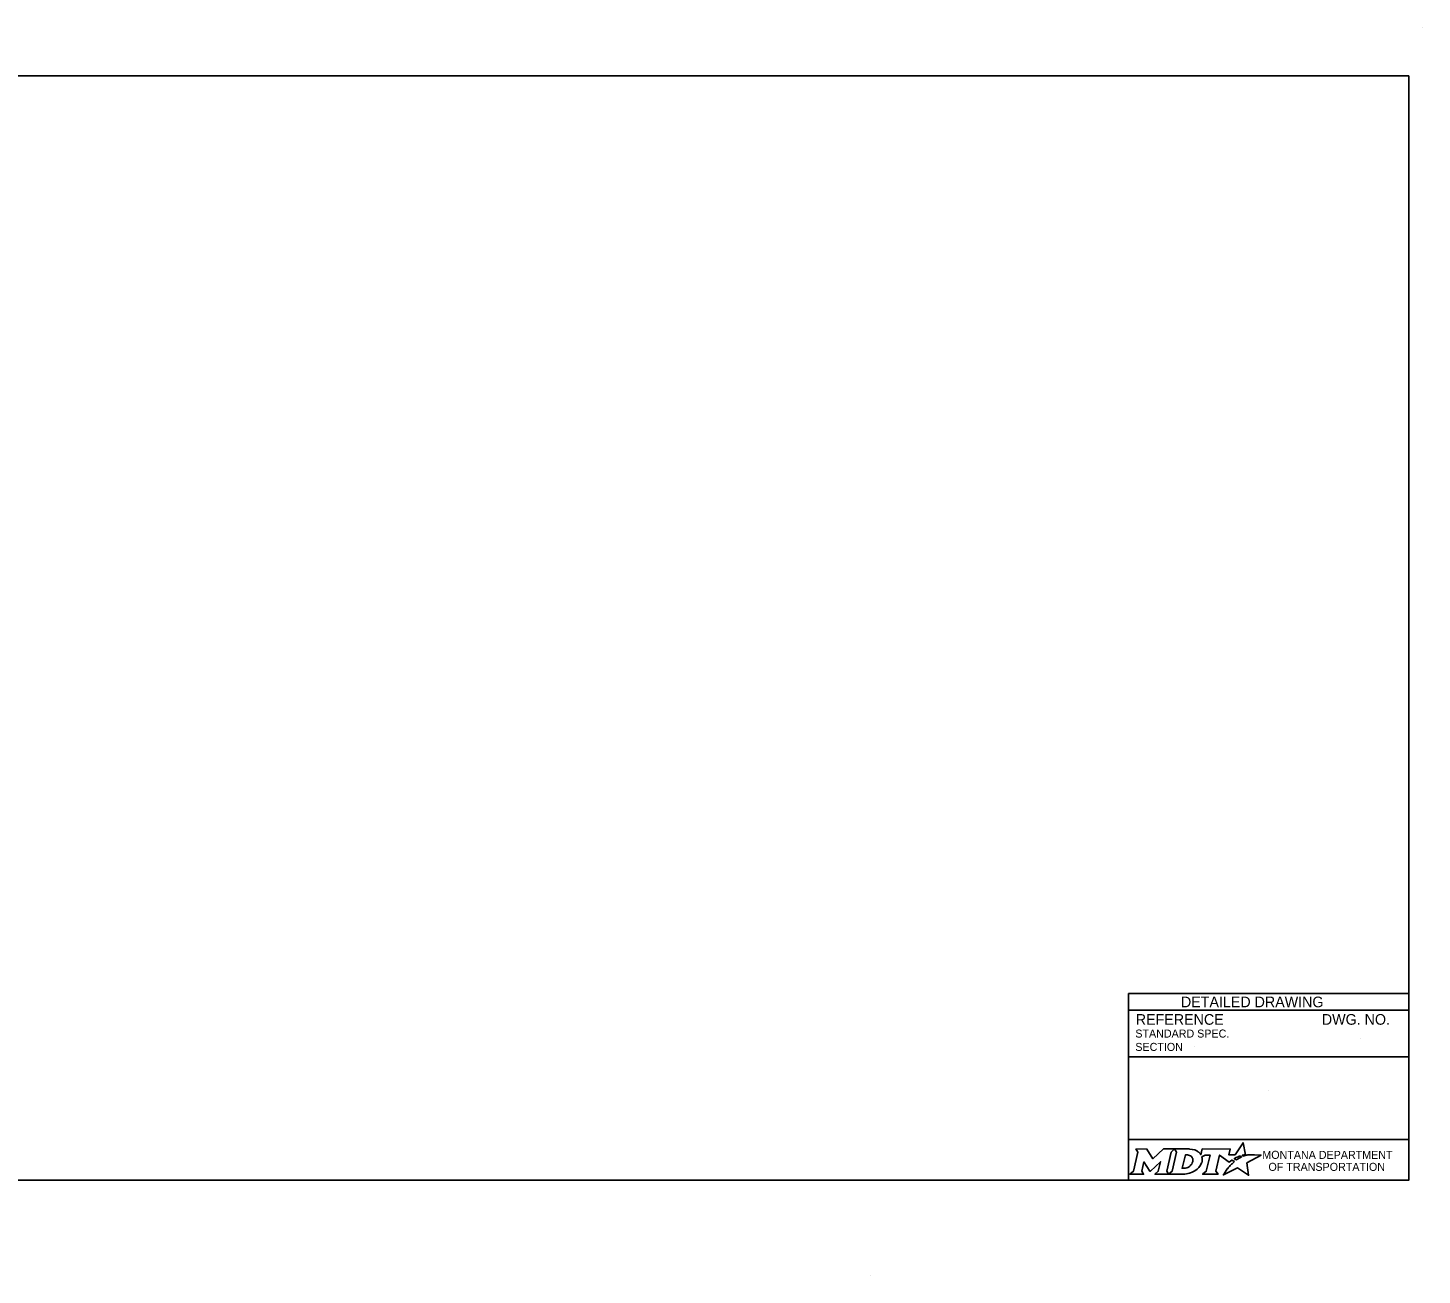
# Model space of a CAD drawing. Extents: x 49991.4 to 50021, y 49987.6 to 50011.4.
# Drawn here: x 50010.59 to 50021.04, y 49999.18 to 50008.52 of the extents above; entities that cross this region are included whole.
import ezdxf

# ---------------------------------------------------------------- set-up
doc = ezdxf.new("R2010")
doc.units = 0
for name, color, linetype in [('Default', 7, 'Continuous'), ('Level 1', 7, 'Continuous'), ('Level 4', 7, 'Continuous')]:
    doc.layers.add(name, color=color, linetype=linetype)

msp = doc.modelspace()

# ---------------------------------------------------------------- linework, layer by layer
at = {"layer": 'Default'}
for points in [[(50018.893, 50000.121), (50018.907, 50000.097), (50018.874, 49999.954), (50018.848, 49999.931), (50018.95, 49999.931), (50018.936, 49999.954), (50018.952, 50000.024), (50018.996, 49999.955), (50019.002, 49999.955), (50019.077, 50000.025), (50019.06, 49999.954), (50019.035, 49999.932), (50019.137, 49999.932), (50019.123, 49999.955), (50019.156, 50000.097)], [(50019.156, 50000.097), (50019.182, 50000.121), (50019.099, 50000.121), (50019.02, 50000.048), (50018.975, 50000.12), (50018.893, 50000.121)], [(50019.295, 50000.121), (50019.182, 50000.121), (50019.196, 50000.098), (50019.163, 49999.954), (50019.137, 49999.932), (50019.248, 49999.932)], [(50019.319, 50000.034), (50019.318, 50000.026), (50019.315, 50000.017), (50019.311, 50000.008), (50019.305, 50000.001), (50019.299, 49999.994), (50019.291, 49999.988), (50019.282, 49999.983), (50019.273, 49999.979), (50019.264, 49999.977), (50019.255, 49999.976), (50019.239, 49999.976), (50019.263, 50000.076), (50019.279, 50000.076), (50019.286, 50000.075), (50019.294, 50000.073), (50019.301, 50000.07), (50019.307, 50000.066), (50019.311, 50000.061), (50019.315, 50000.055), (50019.318, 50000.049), (50019.319, 50000.042), (50019.32, 50000.038), (50019.319, 50000.034)], [(50019.7, 50000.068), (50019.69, 50000.074), (50019.702, 50000.076), (50019.713, 50000.078), (50019.696, 50000.168), (50019.636, 50000.077), (50019.589, 50000.076), (50019.599, 50000.12), (50019.39, 50000.121), (50019.38, 50000.078), (50019.374, 50000.086)], [(50019.387, 50000.062), (50019.411, 50000.075), (50019.448, 50000.075), (50019.42, 49999.954), (50019.392, 49999.931), (50019.508, 49999.931), (50019.491, 49999.954), (50019.52, 50000.075), (50019.591, 50000.023), (50019.612, 50000.038), (50019.632, 50000.027)], [(50019.576, 49999.971), (50019.561, 49999.947), (50019.556, 49999.939), (50019.55, 49999.931), (50019.548, 49999.926), (50019.653, 49999.979), (50019.737, 49999.924), (50019.724, 50000.017), (50019.831, 50000.075), (50019.782, 50000.076), (50019.751, 50000.077), (50019.731, 50000.077), (50019.724, 50000.075), (50019.719, 50000.074), (50019.711, 50000.072), (50019.7, 50000.068)], [(50019.65, 50000.04), (50019.648, 50000.039), (50019.629, 50000.048), (50019.639, 50000.054), (50019.644, 50000.056), (50019.652, 50000.06), (50019.658, 50000.063), (50019.666, 50000.066), (50019.673, 50000.068), (50019.685, 50000.061), (50019.681, 50000.059), (50019.676, 50000.056), (50019.672, 50000.054), (50019.667, 50000.051), (50019.665, 50000.05), (50019.662, 50000.049), (50019.66, 50000.047), (50019.658, 50000.046), (50019.655, 50000.044), (50019.652, 50000.042), (50019.65, 50000.04)], [(50019.59, 49999.987), (50019.59, 49999.987)], [(50019.293, 49999.939), (50019.302, 49999.942), (50019.315, 49999.947), (50019.335, 49999.958)]]:
    msp.add_lwpolyline(points, dxfattribs=at)
for centre, radius, start, end in [((50019.274, 50000.059), 0.118, 300.9103, 339.1383), ((50019.319, 50000.042), 0.0709, 339.5329, 15.8582)]:
    msp.add_arc(centre, radius, start, end, dxfattribs=at)
for centre, major_axis, ratio, start_param, end_param in [((50019.293, 50000.073), (0.0834, -0.0037), 0.568097, 0.61298, 1.570796), ((50019.349, 50000.081), (0.0361, -0.0295), 0.469099, 1.225588, 1.570796), ((50019.583, 49999.979), (-0.00694, -0.00806), 0.008222, 0, 3.137361), ((50019.6, 49999.997), (-0.0098, -0.0102), 0.016458, 3.141593, 6.279097), ((50019.621, 50000.017), (-0.0112, -0.0097), 0.021651, 3.157348, 6.283185), ((50019.248, 50000.08), (0, 0.148), 0.987302, 3.139398, 3.456847)]:
    msp.add_ellipse(centre, major_axis=major_axis, ratio=ratio, start_param=start_param, end_param=end_param, dxfattribs=at)
at = {"layer": 'Level 1'}
for p, q in [((50021.038, 50008.524), (50021.038, 50008.524)), ((50016.9, 49999.176), (50016.9, 49999.176))]:
    msp.add_line(p, q, dxfattribs=at)
msp.add_lwpolyline([(50020.938, 50008.165), (50009.737, 50008.165), (50009.737, 49999.886), (50020.938, 49999.886)], close=True, dxfattribs=at)
at = {"layer": 'Level 4'}
for p, q in [((50020.938, 50001.286), (50018.838, 50001.286)), ((50018.838, 50001.286), (50018.838, 49999.886)), ((50020.938, 50001.161), (50018.838, 50001.161)), ((50020.574, 50000.946), (50020.574, 50000.946)), ((50020.938, 50000.811), (50018.838, 50000.811)), ((50019.332, 50000.886), (50019.332, 50000.886)), ((50019.888, 50000.562), (50019.888, 50000.562)), ((50020.938, 50000.193), (50018.838, 50000.193))]:
    msp.add_line(p, q, dxfattribs=at)

# ---------------------------------------------------------------- texts
at = {"layer": 'Default'}
for s, p in [('MONTANA DEPARTMENT', (50019.84, 50000.047)), ('OF TRANSPORTATION', (50019.886, 49999.957))]:
    msp.add_text(s, height=0.06, rotation=360, dxfattribs=at).set_placement(p)
at = {"layer": 'Level 4'}
for s, height, p in [('DETAILED DRAWING', 0.0799, (50019.23, 50001.183)), ('REFERENCE', 0.08, (50018.891, 50001.052)), ('DWG. NO.', 0.08, (50020.286, 50001.052)), ('STANDARD SPEC.', 0.06, (50018.888, 50000.956)), ('SECTION', 0.06, (50018.888, 50000.856))]:
    msp.add_text(s, height=height, dxfattribs=at).set_placement(p)

doc.saveas('drawing.dxf')
